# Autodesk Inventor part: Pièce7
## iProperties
Shininess: 64.0
Length Units: 11269
Angle Units: 11279
Time Units: 11290
Mass Units: 11283
Length Display Precision: 3
Angle Display Precision: 2
Compacted: True
Part Number: Pièce7
Document SubType Name: Modeling
Created: 2004-06
Material: Par défaut
Designer: laurent
Density: 0.0
Volumn: 0.0
Area: 0.0
PropertySet Name: Model Information
Control State: 0
Master: False
Checked Out: False
Author: laurent
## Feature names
1. Extrusion1
2. Balayage2
3. Balayage3
4. Révolution1 [Revolution]
5. Balayage4
